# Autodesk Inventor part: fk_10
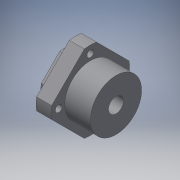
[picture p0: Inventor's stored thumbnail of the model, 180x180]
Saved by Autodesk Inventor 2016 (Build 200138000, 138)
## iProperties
Company: TraceParts S.A.
Created: 2017-01
Part Number: fk_10
Checked By: TraceParts S.A.
Catalog Web Link: www.traceparts.com
Document SubType Name: Modeling
Designer: TraceParts
Material: Типовые
Density: 1 g/cm^3
Appearance: По умолчанию
REFERENCE: FK 10
DESIGN: Свободная опора FK
SUPPLIER: Technische Antriebselemente GmbH - Germany
TraceParts.PartNumber: 80-08072009-138304
TraceParts.PartTitle: Свободная опора FK
TraceParts.InstanceId: 80-08072009-138304EKU3V3O5IF6MT9W43PL41VIPB
TraceParts.PartStatus: Published
TraceParts.PartVersion: 1.0.7
TRACEPARTS: TRACEPARTS
TraceParts.PartLanguage: ru
TraceParts.ClassPath: TEA_GER:/TEA_GER.1/TEA.120/TEA.120.020/80-08072009-138304
Author: TraceParts
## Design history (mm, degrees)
feature "fk_10"
node "Твердое тело1"
node "Твердые тела"
node "Поверхностные тела"
